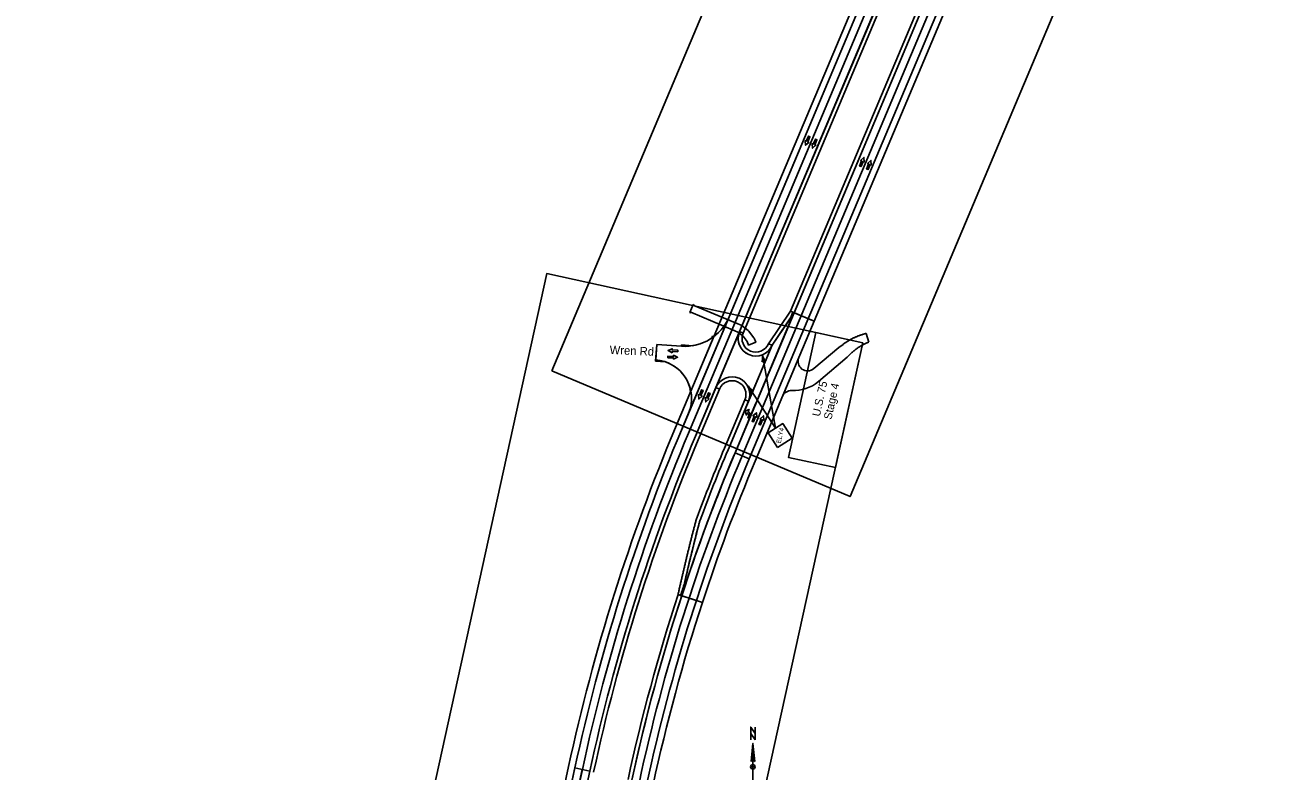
# Model space of a CAD drawing. Extents: x 14107086 to 14122011, y 8637163 to 8671583.
# Drawn here: x 14108117 to 14110053, y 8644899 to 8646064 of the extents above; entities that cross this region are included whole.
import ezdxf

# ---------------------------------------------------------------- set-up
doc = ezdxf.new("R2010")
doc.units = 0
for name, color, linetype in [('Cell', 7, 'Continuous'), ('dsn_culvert_prop', 7, 'Continuous'), ('dsnCellsNorthArrow', 7, 'Continuous'), ('dsnNonPlotable', 7, 'Continuous'), ('dsnPaintExistingBrokenLaneLineWhite', 7, 'Continuous'), ('dsnPaintExistingEdgeLineLeftYellow', 7, 'Continuous'), ('dsnPaintExistingEdgeLineRightWhite', 7, 'Continuous'), ('dsnPaintExistingLaneLineWhite', 7, 'Continuous'), ('dsnPaintPlaceBrokenLaneWhite', 7, 'Continuous'), ('dsnPaintPlaceEdgeLineLeftYellow', 7, 'Continuous'), ('dsnPaintRemoveDoubleCenterLineYellow', 7, 'Continuous'), ('dsnShadingPaved', 7, 'Continuous'), ('dsnStdLabel', 7, 'Continuous'), ('dsnStgShadingPrevPav', 7, 'Continuous'), ('dsnTextFinalPlan', 7, 'Continuous'), ('dsnTextOverlapEven', 7, 'Continuous'), ('Level 2', 7, 'Continuous'), ('Level 5', 7, 'Continuous')]:
    doc.layers.add(name, color=color, linetype=linetype)

msp = doc.modelspace()

# ---------------------------------------------------------------- linework, layer by layer
at = {"layer": 'Cell'}
for p, q in [((14109246.6, 8645460.4), (14109246.8, 8645460.3)), ((14109245.7, 8645457.9), (14109245.4, 8645458))]:
    msp.add_line(p, q, dxfattribs=at)
for points in [[(14109242.5, 8645461.7), (14109248.3, 8645463.7), (14109246.6, 8645460.4)], [(14109242.5, 8645461.7), (14109248.3, 8645463.7), (14109246.6, 8645460.4)], [(14109245.4, 8645458), (14109243.8, 8645454.8), (14109242.5, 8645461.7)], [(14109245.4, 8645458), (14109243.8, 8645454.8), (14109242.5, 8645461.7)], [(14109246.6, 8645460.4), (14109246.8, 8645460.3)], [(14109245.7, 8645457.9), (14109245.4, 8645458)], [(14109249.2, 8645453.5), (14109247.7, 8645450.1), (14109246.4, 8645450.7), (14109247.4, 8645453.1)], [(14109249.2, 8645453.5), (14109247.7, 8645450.1), (14109246.4, 8645450.7), (14109247.4, 8645453.1)]]:
    msp.add_lwpolyline(points, dxfattribs=at)
for centre, major_axis in [((14109244.7, 8645455.5), (-2.12, -4.81)), ((14109244.7, 8645455.5), (-2.12, -4.81)), ((14109244.2, 8645454.6), (-1.49, -3.37)), ((14109244.2, 8645454.6), (-1.49, -3.37))]:
    msp.add_ellipse(centre, major_axis=major_axis, ratio=0.9474, start_param=1.570796, end_param=3.141593, dxfattribs=at)
at = {"layer": 'dsn_culvert_prop'}
msp.add_lwpolyline([(14109161.2, 8645627.4), (14109162.1, 8645627), (14109161.8, 8645626.1), (14109230.5, 8645597.1), (14109230.7, 8645597.4), (14109236.2, 8645595.1), (14109237.5, 8645594.3), (14109247, 8645586.9), (14109248.1, 8645585.8), (14109255.4, 8645576.2), (14109256.1, 8645574.9), (14109258.6, 8645568.7), (14109247.5, 8645564.2), (14109245.3, 8645569.6), (14109239, 8645577.9), (14109230.8, 8645584.3), (14109226, 8645586.3), (14109226.1, 8645586.6), (14109157.4, 8645615.6), (14109157, 8645614.7), (14109156, 8645615.1)], close=True, dxfattribs=at)
at = {"layer": 'dsnCellsNorthArrow'}
for p, q in [((14109254.3, 8644942.2), (14109257.1, 8644914.1)), ((14109254.3, 8644942.2), (14109254.3, 8644869)), ((14109251.5, 8644914.1), (14109251.5, 8644914.1)), ((14109251.6, 8644914.3), (14109252.1, 8644914.9)), ((14109254.3, 8644902.1), (14109254.3, 8644902.1))]:
    msp.add_line(p, q, dxfattribs=at)
msp.add_lwpolyline([(14109257.8, 8644947.9), (14109250.8, 8644957.7), (14109250.8, 8644967.6), (14109257.8, 8644957.7)], close=True, dxfattribs=at)
for points in [[(14109250.8, 8644947.9), (14109250.8, 8644967.6), (14109257.8, 8644957.7), (14109257.8, 8644967.6)], [(14109251.5, 8644914.1), (14109254.3, 8644942.2), (14109254.3, 8644915.5)], [(14109254.3, 8644902.1), (14109254.3, 8644905.6), (14109250.8, 8644905.6)], [(14109257.8, 8644905.6), (14109254.3, 8644905.6), (14109254.3, 8644909.1)]]:
    msp.add_lwpolyline(points, dxfattribs=at)
for centre, start, end in [((14109254.3, 8644905.6), 90, 180), ((14109254.3, 8644905.6), 180, 270), ((14109254.3, 8644912), 90.0204, 143.1257), ((14109254.3, 8644912), 36.8481, 90.0218), ((14109254.3, 8644905.6), 0, 90), ((14109254.3, 8644905.6), 270, 360)]:
    msp.add_arc(centre, 3.52, start, end, dxfattribs=at)
at = {"layer": 'dsnNonPlotable'}
for points in [[(14108940.5, 8645523.8), (14109549.1, 8646968.3), (14110014.5, 8646772.2), (14109405.9, 8645327.7)], [(14108596.1, 8644144.9), (14108932.5, 8645675.8), (14109425.7, 8645567.5), (14109089.3, 8644036.5)]]:
    msp.add_lwpolyline(points, close=True, dxfattribs=at)
at = {"layer": 'dsnPaintExistingBrokenLaneLineWhite'}
for p, q in [((14109153.7, 8645426.8), (14110829.5, 8649404.5)), ((14108623.3, 8643207.7), (14108988, 8644901.3))]:
    msp.add_line(p, q, dxfattribs=at)
msp.add_arc((14111877.8, 8644279.1), 2956, 157.1547, 167.8488, dxfattribs=at)
at = {"layer": 'dsnPaintExistingEdgeLineLeftYellow'}
for p, q in [((14110840.5, 8649399.8), (14109233.5, 8645585.3)), ((14109318.5, 8645614.6), (14110902.3, 8649373.8)), ((14109196.6, 8645497.8), (14109164.7, 8645422.1)), ((14109215.4, 8645400.8), (14109247.3, 8645476.4))]:
    msp.add_line(p, q, dxfattribs=at)
for centre, radius, start, end in [((14111877.8, 8644279.1), 2944, 157.1547, 167.8488), ((14111877.8, 8644279.1), 2889, 157.1547, 159.5027), ((14111945.5, 8644556.1), 2869.5, 165.1655, 167.5885), ((14111877.8, 8644279.1), 2877, 161.9025, 167.8488)]:
    msp.add_arc(centre, radius, start, end, dxfattribs=at)
at = {"layer": 'dsnPaintExistingEdgeLineRightWhite'}
for p, q in [((14110818.4, 8649409.2), (14109217, 8645608.1)), ((14109248.6, 8645386.8), (14110924.4, 8649364.5)), ((14109153.7, 8645457.8), (14109142.6, 8645431.4)), ((14108976.3, 8644903.9), (14108611.6, 8643210.2))]:
    msp.add_line(p, q, dxfattribs=at)
for radius in [2968, 2853]:
    msp.add_arc((14111877.8, 8644279.1), radius, 157.1547, 167.8488, dxfattribs=at)
at = {"layer": 'dsnPaintExistingLaneLineWhite'}
msp.add_line((14109226.5, 8645396.1), (14109258.5, 8645472.2), dxfattribs=at)
msp.add_arc((14111877.8, 8644279.1), 2877, 157.1547, 159.5027, dxfattribs=at)
at = {"layer": 'dsnPaintPlaceBrokenLaneWhite'}
for p, q in [((14110829.5, 8649404.5), (14109153.7, 8645426.8)), ((14109237.5, 8645391.4), (14110913.3, 8649369.2))]:
    msp.add_line(p, q, dxfattribs=at)
msp.add_lwpolyline([(14108987.8, 8644901.6), (14108805.7, 8644054.5), (14108623.3, 8643207.7), (14108376.2, 8642082.7), (14108129.1, 8640957.7)], dxfattribs=at)
for radius in [2956, 2865]:
    msp.add_arc((14111877.8, 8644279.1), radius, 157.1547, 167.8488, dxfattribs=at)
at = {"layer": 'dsnPaintPlaceEdgeLineLeftYellow'}
msp.add_line((14109284.2, 8645564), (14109318.5, 8645614.6), dxfattribs=at)
for centre, radius, start, end in [((14109258.3, 8645574.4), 27.1, 156.2756, 248.0338), ((14109258.8, 8645574.6), 27.5, 247.1547, 337.1547), ((14109221.9, 8645487.1), 27.5, 337.1547, 157.1547)]:
    msp.add_arc(centre, radius, start, end, dxfattribs=at)
at = {"layer": 'dsnPaintRemoveDoubleCenterLineYellow'}
msp.add_line((14110829.5, 8649404.5), (14109153.7, 8645426.8), dxfattribs=at)
msp.add_lwpolyline([(14108987.8, 8644901.6), (14108805.7, 8644054.5), (14108623.3, 8643207.7), (14108129.1, 8640957.7)], dxfattribs=at)
msp.add_arc((14111877.8, 8644279.1), 2956, 157.1547, 167.8488, dxfattribs=at)
at = {"layer": 'dsnShadingPaved'}
for p, q in [((14109142.6, 8645431.4), (14110818.4, 8649409.2)), ((14110840.5, 8649399.8), (14109164.7, 8645422.1)), ((14109226.5, 8645396.1), (14109318.4, 8645614.5)), ((14109318.4, 8645614.5), (14109284.2, 8645564)), ((14109153.7, 8645457.8), (14109217, 8645608.1)), ((14109233.2, 8645584.6), (14109196.6, 8645497.8)), ((14109104.1, 8645564.9), (14109102.5, 8645541)), ((14109142.9, 8645562.3), (14109104.1, 8645564.9)), ((14109247.3, 8645476.4), (14109215.4, 8645400.8)), ((14109248.6, 8645386.8), (14109226.5, 8645396.1)), ((14108999.8, 8644898.8), (14108976.3, 8644903.9))]:
    msp.add_line(p, q, dxfattribs=at)
for points in [[(14109248.6, 8645386.8), (14116822, 8663369.3), (14116799.9, 8663378.6), (14109226.5, 8645396.1)], [(14108999.8, 8644898.8), (14108817.4, 8644052), (14108635.1, 8643205.1), (14108635.1, 8643205.1), (14108387.9, 8642080.1), (14108140.8, 8640955.1), (14108117.4, 8640960.3), (14108364.5, 8642085.3), (14108611.6, 8643210.3), (14108794, 8644057), (14108976.3, 8644903.9)]]:
    msp.add_lwpolyline(points, close=True, dxfattribs=at)
for centre, radius, start, end in [((14109147.9, 8645637.2), 75, 266.1547, 337.1547), ((14109258.3, 8645574.4), 27.1, 158.0339, 248.0338), ((14109258.8, 8645574.6), 27.5, 247.1547, 337.1547), ((14109098.4, 8645481.1), 60, 337.1547, 86.1547), ((14109221.9, 8645487.1), 27.5, 337.1547, 157.1367), ((14111877.8, 8644279.1), 2968, 157.1547, 167.8488), ((14111877.8, 8644279.1), 2944, 157.1547, 167.8488), ((14111877.8, 8644279.1), 2889, 157.1547, 159.5027), ((14111877.8, 8644279.1), 2877, 157.1547, 167.8488), ((14111877.8, 8644279.1), 2853, 157.1547, 167.8488), ((14111877.8, 8644279.1), 2877, 157.1547, 161.9025), ((14111945.5, 8644556.1), 2869.5, 165.1655, 167.5885)]:
    msp.add_arc(centre, radius, start, end, dxfattribs=at)
at = {"layer": 'dsnStdLabel'}
for q in [(14109269.2, 8645549.2), (14109246.9, 8645500.4)]:
    msp.add_line((14109289.5, 8645434.2), q, dxfattribs=at)
msp.add_lwpolyline([(14109292.7, 8645404.2), (14109315.4, 8645418.8), (14109300.9, 8645441.5), (14109278.1, 8645427)], close=True, dxfattribs=at)
for centre, radius, start, end in [((14109246.6, 8645545.2), 22.9, 341.942, 10.0133), ((14109272.5, 8645530.2), 8.86, 82.279, 117.7474), ((14109291.8, 8645553.2), 22.9, 190.0131, 218.0844), ((14109227.6, 8645488), 22.9, 4.7211, 32.7924), ((14109266.1, 8645512.8), 22.9, 212.7923, 240.8635), ((14109257.3, 8645484.2), 8.86, 105.0581, 140.5266)]:
    msp.add_arc(centre, radius, start, end, dxfattribs=at)
at = {"layer": 'dsnStgShadingPrevPav'}
for p, q in [((14109133.4, 8645435.3), (14110809.2, 8649413)), ((14110818.4, 8649409.2), (14109142.6, 8645431.4)), ((14109318.5, 8645614.6), (14109226.5, 8645396.1)), ((14109318.5, 8645614.6), (14109226.5, 8645396.1)), ((14109312.8, 8645606.2), (14109316.7, 8645615.4)), ((14109316.7, 8645615.4), (14109318.5, 8645614.6)), ((14109349.9, 8645601.4), (14109318.5, 8645614.6)), ((14109257.8, 8645382.9), (14109349.9, 8645601.4)), ((14109284.2, 8645564), (14109312.8, 8645606.2)), ((14109157.4, 8645492.3), (14109193.3, 8645577.5)), ((14109191.4, 8645578.2), (14109190.2, 8645575.2)), ((14109193.3, 8645577.5), (14109191.4, 8645578.2)), ((14109196.6, 8645497.8), (14109233.5, 8645585.3)), ((14109233.5, 8645585.3), (14109239, 8645583)), ((14109435.2, 8645568.8), (14109431.1, 8645582.2)), ((14109104.1, 8645564.9), (14109102.3, 8645539)), ((14109142.9, 8645562.3), (14109104.1, 8645564.9)), ((14109143, 8645564.3), (14109142.9, 8645562.3)), ((14109160.2, 8645563.2), (14109143, 8645564.3)), ((14109215.4, 8645400.8), (14109284.2, 8645564)), ((14109284.2, 8645564), (14109247.3, 8645476.4)), ((14109278.6, 8645566.3), (14109284.2, 8645564)), ((14109102.3, 8645539), (14109117.7, 8645538)), ((14109326, 8645544.7), (14109300.4, 8645484)), ((14109356.6, 8645507.3), (14109401.4, 8645545.2)), ((14109401.4, 8645545.2), (14109407.2, 8645550.9)), ((14109196.6, 8645497.8), (14109164.7, 8645422.1)), ((14109202.1, 8645495.4), (14109196.6, 8645497.8)), ((14109202.1, 8645495.4), (14109196.6, 8645497.8)), ((14109156.7, 8645495.7), (14109155.6, 8645493.1)), ((14109155.6, 8645493.1), (14109157.4, 8645492.3)), ((14109170.3, 8645419.8), (14109202.1, 8645495.4)), ((14109209.9, 8645403.1), (14109241.8, 8645478.7)), ((14109241.8, 8645478.7), (14109247.3, 8645476.4)), ((14109247.3, 8645476.4), (14109241.8, 8645478.7)), ((14109247.3, 8645476.4), (14109215.4, 8645400.8)), ((14109175.4, 8645162.3), (14109137.4, 8645174.7)), ((14109141.2, 8645173.4), (14109137.4, 8645174.7)), ((14109143.1, 8645172.8), (14109141.2, 8645173.4)), ((14109143.1, 8645172.8), (14109175.4, 8645162.3)), ((14108601.8, 8643212.3), (14108966.5, 8644906)), ((14108976.3, 8644903.9), (14108611.6, 8643210.2))]:
    msp.add_line(p, q, dxfattribs=at)
for points in [[(14109239, 8645583), (14111389.1, 8650687.1), (14111383.6, 8650689.4), (14109233.5, 8645585.3)], [(14109313, 8645616.9), (14110622.7, 8648725.7), (14110659.7, 8648710.5), (14109349.9, 8645601.4)], [(14109278.6, 8645566.3), (14109313, 8645616.9), (14109316.7, 8645615.4), (14109312.8, 8645606.2), (14109284.2, 8645564)]]:
    msp.add_lwpolyline(points, close=True, dxfattribs=at)
msp.add_lwpolyline([(14109395, 8645565.3), (14109388.4, 8645560.5), (14109349.5, 8645527.5)], dxfattribs=at)
for centre, radius, start, end in [((14109147.9, 8645637.2), 75, 279.4162, 304.2948), ((14109258.8, 8645574.6), 21.5, 157.1547, 247.1547), ((14109258.8, 8645574.6), 21.5, 247.1547, 337.1547), ((14109098.4, 8645481.1), 60, 14.0246, 71.3196), ((14109339.8, 8645538.9), 15, 157.1547, 310.2778), ((14109221.9, 8645487.1), 21.5, 67.1547, 157.1547), ((14109221.9, 8645487.1), 21.5, 337.1547, 67.1547), ((14109317.8, 8645553), 60, 267.2336, 310.2778), ((14109314.2, 8645478.1), 15, 87.2336, 157.1547), ((14111877.8, 8644279.1), 2978, 157.1547, 167.8488), ((14111877.8, 8644279.1), 2968, 157.1547, 167.8488), ((14111877.8, 8644279.1), 2944, 157.1547, 167.8488), ((14111877.8, 8644279.1), 2938, 157.1547, 167.8488), ((14111877.8, 8644279.1), 2895, 157.1547, 159.5027), ((14111877.8, 8644279.1), 2889, 157.1547, 159.5027), ((14111877.8, 8644279.1), 2889, 157.1547, 159.5027), ((14111877.8, 8644279.1), 2877, 157.1547, 161.9025), ((14111877.8, 8644279.1), 2877, 157.1547, 161.9025), ((14111877.8, 8644279.1), 2843, 157.1547, 161.9025), ((14111877.8, 8644279.1), 2879, 161.5026, 161.9025), ((14111877.8, 8644279.1), 2879, 161.5026, 161.9025), ((14111877.8, 8644279.1), 2883, 161.9025, 167.8488), ((14111877.8, 8644279.1), 2843, 161.9025, 167.8488)]:
    msp.add_arc(centre, radius, start, end, dxfattribs=at)
for points in [[(14109431.1, 8645582.2), (14109430.5, 8645582.1), (14109429.2, 8645581.8), (14109427.3, 8645581.3), (14109425.4, 8645580.7), (14109423.5, 8645580.1), (14109421.6, 8645579.5), (14109419.7, 8645578.8), (14109417.8, 8645578.1), (14109416, 8645577.3), (14109414.1, 8645576.5), (14109412.3, 8645575.7), (14109410.5, 8645574.8), (14109408.7, 8645573.9), (14109406.9, 8645573), (14109405.1, 8645572), (14109403.4, 8645571), (14109401.7, 8645569.9), (14109400, 8645568.8), (14109398.3, 8645567.7), (14109396.6, 8645566.5), (14109395.5, 8645565.7), (14109395, 8645565.3)], [(14109407.2, 8645550.9), (14109407.6, 8645551.3), (14109408.4, 8645552), (14109409.6, 8645553.1), (14109410.9, 8645554.2), (14109412.1, 8645555.3), (14109413.4, 8645556.4), (14109414.7, 8645557.4), (14109416, 8645558.4), (14109417.4, 8645559.4), (14109418.8, 8645560.3), (14109420.2, 8645561.2), (14109421.6, 8645562.1), (14109423, 8645563), (14109424.5, 8645563.8), (14109426, 8645564.6), (14109427.5, 8645565.4), (14109429, 8645566.2), (14109430.5, 8645566.9), (14109432, 8645567.6), (14109433.6, 8645568.2), (14109434.7, 8645568.6), (14109435.2, 8645568.8)], [(14109137.4, 8645174.7), (14109137.9, 8645176.7), (14109138.7, 8645180.6), (14109140.1, 8645186.5), (14109141.4, 8645192.5), (14109142.7, 8645198.4), (14109144.1, 8645204.3), (14109145.5, 8645210.2), (14109146.9, 8645216.1), (14109148.3, 8645222), (14109149.7, 8645228), (14109151.1, 8645233.9), (14109152.5, 8645239.8), (14109154, 8645245.7), (14109155.5, 8645251.6), (14109156.9, 8645257.5), (14109158.4, 8645263.4), (14109159.9, 8645269.3), (14109161.5, 8645275.2), (14109163, 8645281.1), (14109164.5, 8645287), (14109165.6, 8645290.9), (14109166.1, 8645292.8)], [(14109171.7, 8645290.7), (14109171.3, 8645289.1), (14109170.4, 8645285.9), (14109169.1, 8645281), (14109167.8, 8645276), (14109166.6, 8645271.1), (14109165.3, 8645266.2), (14109164.1, 8645261.3), (14109162.8, 8645256.4), (14109161.6, 8645251.5), (14109160.4, 8645246.6), (14109159.2, 8645241.7), (14109158, 8645236.8), (14109156.8, 8645231.9), (14109155.6, 8645227), (14109154.4, 8645222), (14109153.2, 8645217.1), (14109152.1, 8645212.2), (14109150.9, 8645207.3), (14109149.8, 8645202.4), (14109148.7, 8645197.4), (14109147.9, 8645194.2), (14109147.5, 8645192.5)], [(14109147.5, 8645192.5), (14109147.9, 8645194.2), (14109148.7, 8645197.4), (14109149.8, 8645202.4), (14109150.9, 8645207.3), (14109152.1, 8645212.2), (14109153.2, 8645217.1), (14109154.4, 8645222), (14109155.6, 8645227), (14109156.8, 8645231.9), (14109158, 8645236.8), (14109159.2, 8645241.7), (14109160.4, 8645246.6), (14109161.6, 8645251.5), (14109162.8, 8645256.4), (14109164.1, 8645261.3), (14109165.3, 8645266.2), (14109166.6, 8645271.1), (14109167.8, 8645276), (14109169.1, 8645281), (14109170.4, 8645285.9), (14109171.3, 8645289.1), (14109171.7, 8645290.7)]]:
    msp.add_open_spline(points, degree=3, dxfattribs=at)
at = {"layer": 'dsnTextOverlapEven'}
for points in [[(14109425.7, 8645567.5), (14109383, 8645372.8), (14109309.7, 8645388.9), (14109352.5, 8645583.6)], [(14109309.7, 8645388.9), (14109352.5, 8645583.6), (14109425.7, 8645567.5), (14109383, 8645372.8)]]:
    msp.add_lwpolyline(points, close=True, dxfattribs=at)
at = {"layer": 'Level 2'}
for points in [[(14109343.3, 8645889.5), (14109340.9, 8645890.5), (14109337.7, 8645882.4), (14109335.9, 8645883.1), (14109336.5, 8645876.1), (14109341.7, 8645880.7), (14109340, 8645881.4)], [(14109354.2, 8645884.9), (14109351.9, 8645885.9), (14109348.6, 8645877.8), (14109346.9, 8645878.5), (14109347.4, 8645871.5), (14109352.6, 8645876.1), (14109350.9, 8645876.8)], [(14109420.8, 8645843.7), (14109423.1, 8645842.8), (14109426.4, 8645850.9), (14109428.1, 8645850.2), (14109427.6, 8645857.2), (14109422.3, 8645852.5), (14109424.1, 8645851.8)], [(14109431.7, 8645839.1), (14109434.1, 8645838.2), (14109437.3, 8645846.3), (14109439.1, 8645845.6), (14109438.5, 8645852.6), (14109433.3, 8645847.9), (14109435, 8645847.2)], [(14109136.9, 8645553.8), (14109137, 8645556.3), (14109128.2, 8645556.6), (14109128.3, 8645558.5), (14109121.9, 8645555.6), (14109128.1, 8645552.2), (14109128.1, 8645554.1)], [(14109121.7, 8645546.9), (14109121.6, 8645544.4), (14109130.4, 8645544.1), (14109130.3, 8645542.2), (14109136.6, 8645545.1), (14109130.5, 8645548.4), (14109130.4, 8645546.6)], [(14109176.4, 8645493.4), (14109174.1, 8645494.3), (14109170.8, 8645486.2), (14109169.1, 8645486.9), (14109169.7, 8645479.9), (14109174.9, 8645484.6), (14109173.2, 8645485.3)], [(14109187.4, 8645488.8), (14109185, 8645489.7), (14109181.8, 8645481.6), (14109180, 8645482.3), (14109180.6, 8645475.3), (14109185.8, 8645480), (14109184.1, 8645480.7)], [(14109252.9, 8645445), (14109255.2, 8645444.1), (14109258.5, 8645452.2), (14109260.2, 8645451.5), (14109259.7, 8645458.5), (14109254.4, 8645453.9), (14109256.2, 8645453.2)], [(14109263.8, 8645440.4), (14109266.2, 8645439.5), (14109269.4, 8645447.6), (14109271.2, 8645446.9), (14109270.6, 8645453.9), (14109265.4, 8645449.2), (14109267.1, 8645448.5)]]:
    msp.add_lwpolyline(points, close=True, dxfattribs=at)
at = {"layer": 'Level 5'}
for points in [[(14109340, 8645881.4), (14109341.7, 8645880.7), (14109336.5, 8645876.1), (14109335.9, 8645883.1), (14109337.7, 8645882.4), (14109340.9, 8645890.5), (14109343.3, 8645889.5), (14109340, 8645881.4)], [(14109350.9, 8645876.8), (14109352.6, 8645876.1), (14109347.4, 8645871.5), (14109346.9, 8645878.5), (14109348.6, 8645877.8), (14109351.9, 8645885.9), (14109354.2, 8645884.9), (14109350.9, 8645876.8)], [(14109424.1, 8645851.8), (14109422.3, 8645852.5), (14109427.6, 8645857.2), (14109428.1, 8645850.2), (14109426.4, 8645850.9), (14109423.1, 8645842.8), (14109420.8, 8645843.7), (14109424.1, 8645851.8)], [(14109435, 8645847.2), (14109433.3, 8645847.9), (14109438.5, 8645852.6), (14109439.1, 8645845.6), (14109437.3, 8645846.3), (14109434.1, 8645838.2), (14109431.7, 8645839.1), (14109435, 8645847.2)], [(14109128.1, 8645554.1), (14109128.1, 8645552.2), (14109121.9, 8645555.6), (14109128.3, 8645558.5), (14109128.2, 8645556.6), (14109137, 8645556.3), (14109136.9, 8645553.8), (14109128.1, 8645554.1)], [(14109130.4, 8645546.6), (14109130.5, 8645548.4), (14109136.6, 8645545.1), (14109130.3, 8645542.2), (14109130.4, 8645544.1), (14109121.6, 8645544.4), (14109121.7, 8645546.9), (14109130.4, 8645546.6)], [(14109173.2, 8645485.3), (14109174.9, 8645484.6), (14109169.7, 8645479.9), (14109169.1, 8645486.9), (14109170.8, 8645486.2), (14109174.1, 8645494.3), (14109176.4, 8645493.4), (14109173.2, 8645485.3)], [(14109184.1, 8645480.7), (14109185.8, 8645480), (14109180.6, 8645475.3), (14109180, 8645482.3), (14109181.8, 8645481.6), (14109185, 8645489.7), (14109187.4, 8645488.8), (14109184.1, 8645480.7)], [(14109256.2, 8645453.2), (14109254.4, 8645453.9), (14109259.7, 8645458.5), (14109260.2, 8645451.5), (14109258.5, 8645452.2), (14109255.2, 8645444.1), (14109252.9, 8645445), (14109256.2, 8645453.2)], [(14109267.1, 8645448.5), (14109265.4, 8645449.2), (14109270.6, 8645453.9), (14109271.2, 8645446.9), (14109269.4, 8645447.6), (14109266.2, 8645439.5), (14109263.8, 8645440.4), (14109267.1, 8645448.5)]]:
    msp.add_lwpolyline(points, dxfattribs=at)

# ---------------------------------------------------------------- texts
at = {"layer": 'dsnStdLabel'}
msp.add_text('ELY4', height=7.2, rotation=77.6078, dxfattribs=at).set_placement((14109297.7, 8645410.3))
at = {"layer": 'dsnTextFinalPlan'}
msp.add_text('Wren Rd', height=13.12, rotation=357.6374, dxfattribs=at).set_placement((14109030.4, 8645550.3))
at = {"layer": 'dsnTextOverlapEven'}
for s, p in [('U.S. 75', (14109358.7, 8645451.9)), ('Stage 4', (14109376.9, 8645447))]:
    msp.add_text(s, height=12.5, rotation=77.6078, dxfattribs=at).set_placement(p)

doc.saveas('drawing.dxf')
